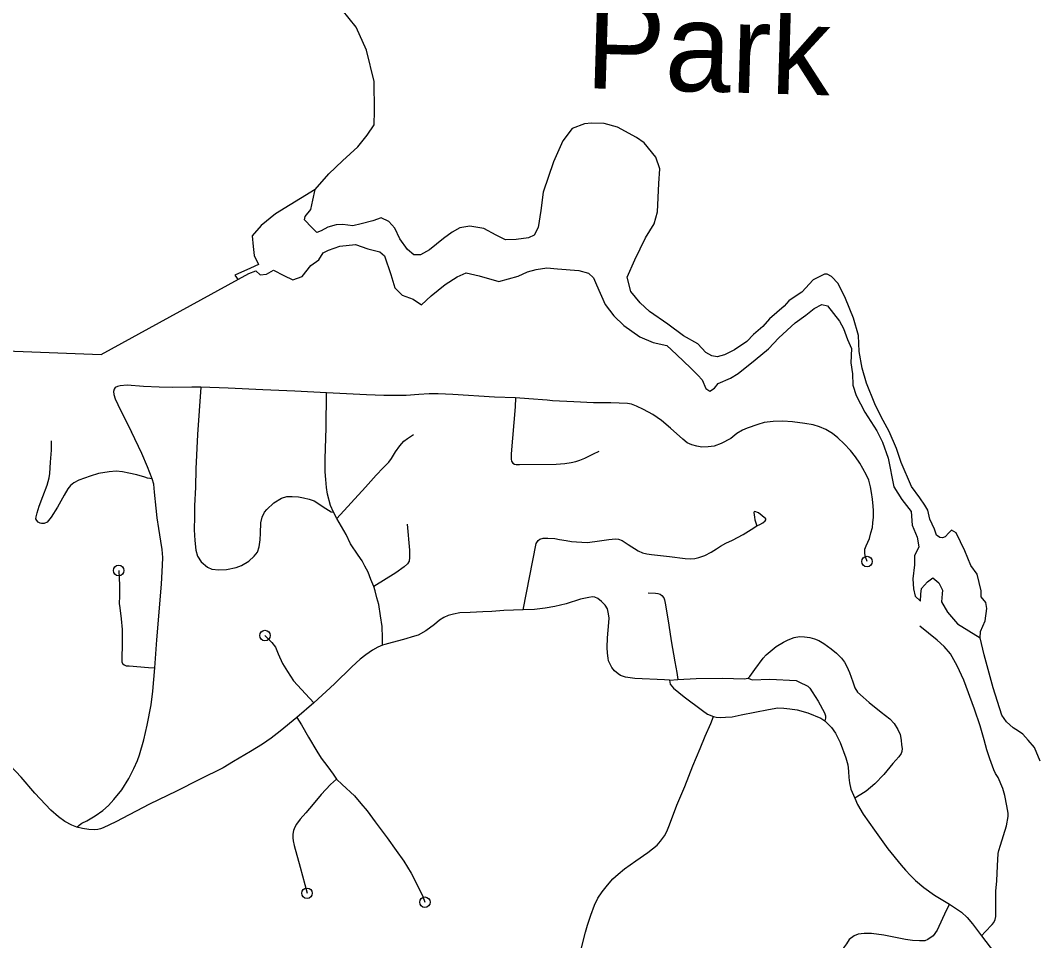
# Model space of a CAD drawing. Extents: x 653372 to 905732, y 627442 to 787275.
# Drawn here: x 707761 to 712584, y 736268 to 740638 of the extents above; entities that cross this region are included whole.
import ezdxf

# ---------------------------------------------------------------- set-up
doc = ezdxf.new("R2010")
doc.units = 0
for name, color, linetype in [('31', 7, 'Continuous'), ('32', 7, 'Continuous'), ('46', 7, 'Continuous'), ('6', 7, 'Continuous'), ('7', 7, 'Continuous'), ('9', 7, 'Continuous')]:
    doc.layers.add(name, color=color, linetype=linetype)

msp = doc.modelspace()

# ---------------------------------------------------------------- linework, layer by layer
at = {"layer": '31'}
for points in [[(711778.9, 738068.5), (711771.4, 738090.2), (711768.7, 738106), (711767.9, 738119.9), (711768.7, 738127.4), (711774.9, 738142.4), (711790.4, 738178.4), (711796.9, 738204.7), (711804.6, 738230.3), (711806.5, 738253), (711809.2, 738279.3), (711808.9, 738310.9), (711808.3, 738331.7), (711804.8, 738364.2), (711800.8, 738397.1), (711795.9, 738422.5), (711787.4, 738455.5), (711776.8, 738479.1), (711759.5, 738510.5), (711745.1, 738536.2), (711724.6, 738566.4), (711700.9, 738595.5), (711669.7, 738626.7), (711640.3, 738655.9), (711615.1, 738676.2), (711583.6, 738696.1), (711553.7, 738708.9), (711522.5, 738717.4), (711483, 738723.7), (711425.3, 738731.1), (711380, 738734.3), (711334, 738733.8), (711290.4, 738728.8), (711260.5, 738719), (711210.2, 738702.2), (711187.8, 738691.6), (711161.5, 738676.6), (711132, 738652.3), (711086.6, 738628.4), (711052.8, 738616.8), (711025.6, 738612.6), (710994.1, 738612.3), (710970.9, 738616.1), (710947.2, 738623.2), (710926, 738631.4), (710905.5, 738649.6), (710845.4, 738701.8), (710803.6, 738737.8), (710762.3, 738766.7), (710717.6, 738790.1), (710684.1, 738806.3), (710661.7, 738815.7), (710642.2, 738818.9), (710563, 738821.9), (710481.1, 738822.4), (710387.1, 738826.5), (710286.4, 738830.8), (710260.7, 738834.1), (710173.7, 738841), (710110.3, 738845.2), (710010.4, 738848.5), (709814, 738862), (709742.9, 738864.8), (709701.3, 738864.1), (709651.4, 738861.2), (709591.4, 738857.3), (709544.2, 738856.2), (709485.3, 738857.4), (709403.5, 738860.5), (709214.4, 738868.9), (709063.8, 738878.2), (708910.9, 738884.1), (708746.7, 738891.5), (708616.8, 738896.1), (708574.5, 738896.1), (708485.1, 738895.6), (708420.2, 738896.3), (708346, 738899.8), (708267.8, 738905.3), (708234.9, 738903.1), (708221.6, 738899.1), (708211.4, 738894.4), (708205.5, 738887.6), (708203.2, 738875.7), (708204.1, 738862.4), (708211, 738840.8), (708236.5, 738786.5), (708287.6, 738684.1)], [(708616.8, 738896.1), (708601.9, 738671.3), (708594.2, 738509.3), (708591.5, 738422.4), (708588.1, 738332.8), (708588.1, 738283), (708585.4, 738219.1), (708588.9, 738169.2), (708593.9, 738122.8), (708600.9, 738094.1), (708618.6, 738066.6)], [(709479.2, 737671), (709479.6, 737706.3), (709477.7, 737760.4), (709470.6, 737810.4), (709461.6, 737864), (709453.3, 737896.3), (709444.3, 737930), (709437.8, 737949.4), (709424.6, 737984), (709410.7, 738018.5), (709395.9, 738046.7), (709382.4, 738071.3), (709364.1, 738098.9), (709328, 738152.7), (709306.6, 738197.7), (709262.6, 738272.3), (709247.3, 738303.5), (709233.5, 738335), (709218.8, 738388.5), (709213.7, 738419.6), (709210.6, 738458.8), (709208.1, 738493.8), (709207.8, 738556.9), (709211.5, 738702.7), (709214.4, 738868.9)], [(710110.3, 738845.2), (710109.4, 738802.3), (710090.6, 738580.6), (710089.8, 738554.5), (710091.3, 738545.4), (710097.4, 738536.2), (710106.2, 738530.1), (710113.4, 738529.9), (710130.1, 738529.4), (710303.4, 738530.9), (710344.2, 738534.2), (710374.6, 738538.3), (710397.7, 738543.9), (710416, 738549.2), (710439.3, 738559.3), (710480, 738579.3), (710507, 738592.5)], [(708029.3, 736807.3), (708039.8, 736817.2), (708052.8, 736826.1), (708076, 736838.2), (708116.5, 736861.2), (708152.8, 736887.1), (708179.8, 736909.8), (708204.9, 736938.2), (708243.2, 736984.7), (708276.1, 737037.8), (708298.9, 737085.5), (708316.4, 737124.1), (708326.5, 737150.2), (708347.1, 737222.2), (708363.4, 737291.5), (708381.2, 737387.7), (708390.3, 737453.6), (708399.3, 737563.2), (708409, 737696.6), (708430.5, 737960.6), (708435.3, 738051.1), (708436.4, 738087.4), (708434, 738125.2), (708427.3, 738165.2), (708418.5, 738225.2), (708410.8, 738276.7), (708405.7, 738321.7), (708398.1, 738398), (708394.2, 738435.9), (708386.5, 738462), (708364.7, 738518.8), (708337.4, 738580.9), (708287.6, 738684.1)], [(709262.6, 738272.3), (709399, 738421.8), (709449.8, 738478.5), (709482.5, 738512.8), (709510.2, 738540.9), (709522.4, 738557.6), (709541.2, 738589), (709561.9, 738617.6), (709580.7, 738639.4), (709597.5, 738652.8), (709626.5, 738672.2)], [(708930.3, 738316.2), (708964, 738347.2), (708999.5, 738369.6), (709025.3, 738376.7), (709050.9, 738377.3), (709080.1, 738376.5), (709104.8, 738371.5), (709131.7, 738365), (709154.9, 738356.4), (709209.8, 738320.6), (709236, 738304.6), (709247.3, 738303.5)], [(711256.1, 738238), (711270.1, 738243.9), (711284.9, 738251.6), (711295.9, 738261.4), (711299.2, 738266.9), (711299.3, 738272), (711263, 738299.5), (711246.8, 738306.3), (711243.6, 738303.9), (711241.6, 738300.8), (711243.2, 738290), (711244.1, 738279.9), (711246.9, 738267.2), (711256.1, 738238)], [(709596.6, 738245.3), (709607.2, 738122.6), (709607.6, 738088.4), (709605.6, 738070), (709598.1, 738058.1), (709582, 738042.9), (709542.8, 738015.6), (709437.8, 737949.4)], [(710147.6, 737839.8), (710209.2, 738154.9), (710217.8, 738169.1), (710226.2, 738175.2), (710241.4, 738179.1), (710264.1, 738179.7), (710297.5, 738177.5), (710320, 738173), (710350.7, 738168.3), (710377.1, 738163.7), (710399.7, 738161.8), (710424.9, 738161), (710451.3, 738159.6), (710486.7, 738163), (710553.3, 738172.9), (710585.5, 738176.4), (710599.4, 738175.3), (710616.8, 738168.5), (710645.8, 738150), (710692.2, 738119.6), (710712.7, 738110.2), (710733.3, 738105.1), (710756.5, 738101.3), (710841.9, 738092.4), (710916, 738082.6), (710939.9, 738081.3), (710962, 738083.1), (710980.4, 738088.3), (711009, 738097.5), (711038.9, 738113), (711065.2, 738129.2), (711083.2, 738141.3), (711108.3, 738156.3), (711140.8, 738169.8), (711190.6, 738196.5), (711229.1, 738221.1), (711256.1, 738238)], [(708227.5, 738026.1), (708231.8, 737954.7), (708231.4, 737903.8), (708230.4, 737870), (708233.3, 737848.9), (708239.9, 737795.8), (708244.8, 737746.6), (708244.2, 737668.9), (708243.2, 737615.8), (708243.1, 737592.4), (708246.4, 737584.1), (708254.3, 737577.5), (708262.4, 737573.7), (708277.6, 737572.7), (708368.4, 737565.3), (708399.3, 737563.2)], [(710841.2, 737505.9), (710818.1, 737506.4), (710677.2, 737513.4), (710632.4, 737519.7), (710609.3, 737527.1), (710597.9, 737535.8), (710580.6, 737550.2), (710567.7, 737566.1), (710560.9, 737578), (710552.6, 737596.6), (710550.2, 737610.5), (710547.5, 737633.4), (710546.1, 737660.7), (710547.5, 737705.6), (710553.6, 737779.3), (710555.3, 737800.4), (710552.6, 737820.4), (710546.6, 737843.4), (710536.1, 737860.9), (710519.4, 737879.2), (710501.5, 737893.1), (710486.7, 737899.1), (710475.6, 737901.1), (710459.4, 737898.2), (710419.2, 737890), (710351.7, 737867.6), (710297.4, 737855.3), (710251.1, 737847.3), (710201.5, 737841.5), (710147.6, 737839.8), (710054.7, 737836.5), (709998.5, 737832.1), (709955.7, 737829.5), (709895.4, 737826.8), (709847, 737824.4), (709815.8, 737818.7), (709790.6, 737811.7), (709770.3, 737802.8), (709750.5, 737790.6), (709726, 737769.2), (709684.5, 737739.3), (709648.4, 737719.8), (709631.1, 737714.8), (709578.4, 737698.6), (709524.6, 737684.7), (709491, 737675.1), (709479.2, 737671), (709457.5, 737662.3), (709432.1, 737647.5), (709399.8, 737625.7), (709373.6, 737604.8), (709334.2, 737568.8), (709251.8, 737487.3), (709153.6, 737397.5), (709073.2, 737328.3), (708994.6, 737263.4), (708950.8, 737229.7), (708910, 737202.1), (708852.8, 737166), (708772.6, 737119.5), (708722.8, 737089.9), (708611, 737033.4), (708501.6, 736977.8), (708373.9, 736917), (708213.7, 736832.9), (708153.9, 736804.1), (708141.6, 736799.5), (708128.7, 736796.6), (708112.6, 736794.8), (708085.4, 736796.2), (708056.3, 736800.4), (708029.3, 736807.3), (708005.2, 736816.9)], [(710740.5, 737920), (710775.5, 737919), (710786.5, 737917.5), (710796.4, 737914.4), (710805.7, 737908.1), (710814.2, 737896.7), (710818.4, 737887.1), (710822.7, 737863.7), (710838.1, 737767.1), (710848.6, 737692.3), (710866.7, 737592.7), (710876.9, 737542.4), (710881.5, 737508.6)], [(712321.4, 736292.2), (712339.1, 736310.2), (712373.2, 736344.7), (712380.2, 736355.5), (712386.1, 736369.4), (712389.6, 736383.4), (712390.8, 736403.5), (712389.6, 736463.5), (712390.2, 736503.9), (712394.7, 736553.3), (712397.4, 736623.6), (712401.1, 736682.9), (712404.5, 736696.2), (712412, 736721.3), (712441.1, 736814.1), (712448.5, 736857.3), (712447.9, 736873.5), (712442.1, 736909.5), (712432.8, 736958.4), (712423.3, 736991.1), (712400.5, 737043.8), (712388, 737062), (712380.7, 737079.3), (712361.3, 737131.3), (712347.9, 737175.2), (712334.7, 737222.7), (712315.3, 737289.3), (712288.3, 737367.4), (712238.6, 737505.9), (712207.2, 737574), (712175.6, 737630.2), (712144.5, 737665.8), (712112.3, 737695.6), (712029.3, 737761.7)], [(708921.7, 737717.1), (708954.2, 737684.8), (708972, 737662.3), (708984.5, 737629.9), (709005.2, 737584.4), (709028.3, 737546), (709056.8, 737501.8), (709114.7, 737440.3), (709153.6, 737397.5)], [(710841.2, 737505.9), (710881.5, 737508.6), (710968.4, 737513.7), (711092, 737515.5), (711144.6, 737513.9), (711195.3, 737511.8), (711205.4, 737512.7), (711214, 737514.9), (711223.4, 737522.6), (711247.1, 737556.1), (711285.4, 737610.1), (711299.9, 737624.9), (711348.2, 737665.1), (711381.8, 737685.5), (711404.8, 737697.6), (711432.7, 737707.8), (711457.9, 737712), (711482.3, 737711.2), (711506.7, 737708), (711529.1, 737701.3), (711550.3, 737693.9), (711573.1, 737679.7), (711609.1, 737654.2), (711634, 737633.2), (711657.8, 737610.5), (711672.5, 737591.1), (711682.3, 737570), (711696.1, 737541.4), (711710.7, 737498.2), (711720.2, 737468.5), (711733.1, 737449.1), (711760.5, 737425.1), (711789.4, 737398.7), (711846.2, 737354.1), (711887.4, 737321.7), (711907.6, 737300.3), (711925.7, 737271.6), (711936, 737246.8), (711940.7, 737220.4), (711943.1, 737198.9), (711945, 737181.2), (711943.9, 737165.9), (711940.6, 737156.8), (711929.8, 737141.8), (711901.2, 737109.2), (711858.1, 737057.2), (711815.8, 737013.9), (711774.4, 736979), (711749.4, 736963.3), (711720.2, 736945.8)], [(710841.2, 737505.9), (710845.2, 737486.7), (710860.1, 737468.1), (710910.5, 737426.7), (710997.4, 737361.5), (711021.4, 737344.4), (711050.2, 737332.4), (711063.6, 737329.6), (711085.4, 737328.9), (711107.7, 737330.2), (711138.1, 737331.6), (711181.8, 737340.5), (711310.5, 737366.6), (711355.2, 737373.4), (711383.8, 737372.3), (711412.2, 737369.9), (711446.5, 737364.3), (711498.3, 737349.8), (711559.3, 737324.7), (711578.8, 737311.6), (711610.6, 737280.5), (711628.8, 737253.6), (711651.1, 737209.4), (711678.8, 737136.9), (711687.8, 737103.1), (711690, 737089.1), (711691.3, 737071.4), (711692.4, 737044), (711695.2, 737018.5), (711702.5, 736987.4), (711720.2, 736945.8), (711734.2, 736914.4), (711760.9, 736869.1), (711814, 736793.2), (711877.5, 736705.1), (711940.5, 736627.1), (711961.6, 736603.6), (711984.4, 736577.2), (712009.5, 736554.2), (712048.9, 736520.3), (712099.1, 736485), (712170.1, 736441.1), (712227.7, 736403.4), (712254.1, 736379.1), (712279.5, 736348.3), (712321.4, 736292.2), (712441, 736137.1)], [(711214, 737514.9), (711225.7, 737509.5), (711233.6, 737507.4), (711317.5, 737510.4), (711442.7, 737503), (711455.4, 737497.7), (711497.5, 737476.2), (711507.8, 737467.9), (711518.8, 737450.5), (711546.8, 737405), (711577.6, 737350.8), (711581.4, 737336), (711581.1, 737325.6), (711578.8, 737311.6)], [(709073.2, 737328.3), (709095.1, 737293.5), (709128.9, 737235.1), (709167.6, 737167.7), (709188.5, 737135.1), (709220, 737094.2), (709245.8, 737059.2), (709261.8, 737035.5), (709288.4, 737009.3), (709345.9, 736955.9), (709376.8, 736919.3), (709407.1, 736885.7), (709445.4, 736832.2), (709501.3, 736756.8), (709543.9, 736696.6), (709580.2, 736646.8), (709615.3, 736588.3), (709643.4, 736533.6), (709671.6, 736477.5), (709680.9, 736451)], [(710421.8, 736227.5), (710442.2, 736308.7), (710452.2, 736342.4), (710467.6, 736390), (710486, 736436.4), (710501.9, 736469.8), (710521.8, 736501.2), (710546.7, 736531.4), (710572.5, 736561.6), (710598.2, 736584.7), (710627.9, 736609.8), (710680.9, 736647.1), (710738.4, 736687.3), (710782.3, 736722), (710798.9, 736741.4), (710817.6, 736766.8), (710828.2, 736786.5), (710841.1, 736819), (710876.8, 736911.8), (710914.1, 737000.6), (710952.4, 737099.3), (710986.6, 737181.7), (711010.1, 737240), (711038.2, 737299.5), (711050.2, 737332.4)], [(708005.2, 736816.9), (707972.4, 736834), (707942.5, 736856), (707905.7, 736888.3), (707829.2, 736968.9), (707764.3, 737045.3), (707713.3, 737100.7)], [(709261.8, 737035.5), (709232.9, 737009.9), (709187.9, 736961.8), (709151.1, 736916), (709115, 736875.9), (709088.3, 736845.9), (709071.3, 736822), (709063.2, 736807.4), (709057.6, 736791.2), (709054.6, 736774.2), (709054.4, 736756.4), (709056.1, 736742.1), (709060.2, 736720.9), (709088, 736617.8), (709121.4, 736493.6)]]:
    msp.add_lwpolyline(points, dxfattribs=at)
for centre in [(711778.9, 738068.5), (708227.5, 738026.1), (708921.7, 737717.1), (709121.4, 736493.6), (709680.9, 736451)]:
    msp.add_circle(centre, 25, dxfattribs=at)
at = {"layer": '32'}
for points in [[(708386.5, 738462), (708364.5, 738464.1), (708351.1, 738468.7), (708313.8, 738480.5), (708275.6, 738488.1), (708245.2, 738494), (708216.1, 738497), (708181.9, 738495.2), (708131.1, 738486), (708092.4, 738474.4), (708038.5, 738455.4), (708014.6, 738441.8), (707998.6, 738429.5), (707986, 738413.5), (707968.7, 738383.5), (707936.5, 738326.8), (707907.3, 738280), (707888.9, 738255.7), (707874.5, 738249.7), (707861, 738248.7), (707854.6, 738250.3), (707845.6, 738255.5), (707839.4, 738263.6), (707834.7, 738271.5), (707836.3, 738280.7), (707840.5, 738299.8), (707850.7, 738331.5), (707867, 738376.6), (707887.8, 738430.7), (707898.1, 738466.7), (707901.6, 738486.5), (707904.6, 738540.5), (707908.4, 738596.6), (707908.9, 738635), (707909, 738641)], [(708618.6, 738066.6), (708649.1, 738042.2), (708670.2, 738032.3), (708702.8, 738029.2), (708739.8, 738030.2), (708784.9, 738040.3), (708810.8, 738049.4), (708844.8, 738069.8), (708869.8, 738094.6), (708886, 738112.6), (708893.8, 738138.7), (708898.4, 738172), (708900, 738202.6), (708901.5, 738252.3), (708908, 738279.9), (708920.1, 738303.7), (708930.3, 738316.2)]]:
    msp.add_lwpolyline(points, dxfattribs=at)
at = {"layer": '46'}
msp.add_lwpolyline([(712170.1, 736441.1), (712155.1, 736411.6), (712111.3, 736318), (712092.8, 736292.3), (712067.2, 736274.7), (712052.9, 736267.8), (712027.9, 736267.9), (711994.9, 736268.9), (711961.4, 736274.8), (711858.6, 736294.4), (711800.8, 736302.9), (711765.3, 736303.3), (711737, 736299.3), (711717.4, 736291.9), (711694.8, 736273.6), (711680.7, 736253.3), (711667.9, 736234.7), (711665.8, 736223.7), (711665.9, 736207.2)], dxfattribs=at)
at = {"layer": '6'}
for points in [[(706333.6, 739120.4), (708144.6, 739051.7), (708845.8, 739435.6), (708878.3, 739449.2), (708899, 739429), (708929.3, 739432.6), (708962.4, 739452), (709010.8, 739426.6), (709054.6, 739405.9), (709098, 739422.2), (709138.7, 739473.7), (709176.6, 739500.9), (709198.6, 739534), (709222.7, 739547), (709277, 739566.1), (709351.6, 739573.4), (709409.9, 739552.6), (709466.9, 739539.1), (709488.6, 739520.1), (709518.5, 739430.6), (709537.5, 739368.2), (709573.6, 739333), (709624.3, 739314), (709665.1, 739286.9), (709711.1, 739330.3), (709776.2, 739384.6), (709833.1, 739419.9), (709876.5, 739439), (709938.9, 739425.4), (710031.2, 739398.4), (710123.4, 739422.8), (710167.3, 739443.5), (710208.2, 739454.9), (710259.6, 739463.6), (710310.5, 739458.2), (710410.9, 739450.1), (710456.7, 739438.1), (710481.4, 739415.5), (710495, 739382.4), (710535.5, 739288.7), (710576.5, 739235.9), (710625.4, 739189.9), (710701.4, 739135.6), (710763.8, 739108.6), (710828.9, 739095), (710875, 739051.7), (710942.9, 738986.6), (710975.4, 738954.1), (710996.5, 738930.5), (711013.3, 738889.6), (711032.7, 738877.8), (711055.4, 738891.8), (711073.1, 738913.4), (711130.8, 738939.8), (711167.9, 738961.8), (711248.7, 739025.5), (711311, 739078.9), (711360.2, 739131.1), (711437.1, 739201.4), (711488.8, 739237.8), (711528.6, 739270.3), (711564.3, 739289.7), (711591, 739282.7), (711648, 739209.5), (711667.1, 739174.3), (711686, 739122.8), (711705.1, 739079.3)], [(711705.1, 739079.3), (711702.4, 739012.1), (711710.6, 738960), (711712, 738905.4), (711726.9, 738856.9), (711767.6, 738778.2), (711825.7, 738688.6), (711852.8, 738635.7), (711879, 738558.6), (711906.2, 738423), (711944.2, 738363.3), (711987.6, 738306.4), (711993.1, 738241.3), (712016.7, 738184.1), (712024.5, 738138.2), (712004.3, 738096.2), (712003.9, 738052.8), (711995.4, 737985.8), (712000, 737939.1), (712006.9, 737904.9), (712033, 737881.2), (712034.4, 737913.7), (712036.7, 737940.2), (712066.5, 737972.7), (712090.9, 737991.7), (712118.9, 737967.6), (712137.1, 737932.1), (712135.4, 737915.7), (712131.7, 737877.8), (712160.6, 737828.3), (712207.4, 737773.1), (712316.2, 737705.6)]]:
    msp.add_lwpolyline(points, dxfattribs=at)
at = {"layer": '7'}
msp.add_lwpolyline([(709160.3, 739835.7), (708971.3, 739719.7), (708904.4, 739664), (708860.3, 739615.1), (708866.3, 739564.7), (708870, 739521.9), (708891.3, 739478.6), (708853.2, 739462.2), (708778.6, 739428.4), (708794.5, 739405.6)], dxfattribs=at)
at = {"layer": '9'}
for points in [[(709769.6, 739602.3), (709702.5, 739549.2), (709659.8, 739524.2), (709628.3, 739525.2), (709597.6, 739549.7), (709562.4, 739600.6), (709537.7, 739651.2), (709509.8, 739683.5), (709473.6, 739700.4), (709433.8, 739685.8), (709378.3, 739671.7), (709338.7, 739662.4), (709291.7, 739669.1), (709260.2, 739667.4), (709220.5, 739655.5), (709188.5, 739638.1), (709167.3, 739630.8), (709144.4, 739655.1), (709108.7, 739690.3), (709111.8, 739706), (709139.1, 739739.3), (709148.3, 739783.6), (709160.3, 739835.7), (709225.5, 739909.8), (709290.3, 739970.8), (709363.1, 740036.9), (709406.7, 740093.3), (709439.7, 740142.1), (709441.6, 740207.7), (709440.6, 740348.1), (709403.1, 740496.1), (709353.9, 740605.2), (709288.2, 740688.5)], [(711523.8, 739405.9), (711469.6, 739347.2), (711437.5, 739327.2), (711408.1, 739307), (711386.3, 739281.5), (711316.3, 739220.6), (711283.8, 739184.9), (711240.6, 739146.8), (711208.2, 739113.7), (711149.3, 739073.5), (711102.2, 739050.7), (711067.8, 739041.2), (711041.7, 739044.6), (711013.3, 739061.2), (710975.2, 739101.7), (710908.2, 739140.5), (710833.8, 739195.2), (710746.4, 739255.5), (710703, 739296.2), (710657.4, 739350), (710641.1, 739418.7), (710677.7, 739501.5), (710728, 739605), (710769.4, 739671.9), (710784.2, 739729.2), (710790.9, 739862.8), (710795.6, 739933.5), (710776.3, 739989.2), (710720.6, 740056.4), (710684.6, 740081.1), (710594.3, 740131.1), (710531.9, 740148.7), (710471.7, 740150.5), (710437.4, 740146.3), (710379.1, 740124.4), (710335.3, 740065.4), (710290.4, 739967), (710241.5, 739821.6), (710231, 739735.3), (710218.1, 739654.4), (710198.7, 739618.2), (710172.1, 739605.9), (710113.1, 739597.2), (710063.2, 739596.1), (710019.3, 739618.4), (709959.9, 739649), (709894.7, 739661.5), (709847.2, 739652.4), (709809.9, 739632.5), (709769.6, 739602.3)], [(712600.8, 737121.1), (712573.8, 737184.9), (712543.4, 737219.9), (712518.1, 737249.5), (712497.5, 737263.2), (712471.8, 737279.7), (712441.1, 737306.9), (712418.5, 737339.1), (712377.8, 737468.8), (712335.3, 737624.9), (712316.2, 737705.6), (712317.1, 737737), (712340.2, 737787.4), (712347.1, 737844.9), (712342.8, 737873.9), (712320, 737900.8), (712320.8, 737929.7), (712302.2, 738008.9), (712272, 738049.2), (712243.2, 738119.2), (712201.2, 738204.5), (712180, 738217.2), (712166.5, 738204.5), (712150.2, 738186.6), (712136.9, 738181.8), (712123.8, 738182.2), (712108.4, 738193.1), (712098.8, 738222.3), (712076.7, 738270.2), (712067.4, 738312.4), (712052.4, 738336.5), (712029.9, 738371.3), (711989.5, 738425), (711940.5, 738539.2), (711918.9, 738605.5), (711884.6, 738685.2), (711845.2, 738756.1), (711815.6, 738817.3), (711776.6, 738915.6), (711755.1, 738987.1), (711741.8, 739066.2), (711738.8, 739142.3), (711715.1, 739224.4), (711675.9, 739317.4), (711641.3, 739389.2), (711610.8, 739421.6), (711590.2, 739432.8), (711577.1, 739433.1), (711561.1, 739425.8), (711523.8, 739405.9)]]:
    msp.add_lwpolyline(points, dxfattribs=at)

# ---------------------------------------------------------------- texts
at = {"layer": '7'}
msp.add_text('Park', height=422.4, rotation=358.28, dxfattribs=at).set_placement((710439.3, 740316.4))

doc.saveas('drawing.dxf')
